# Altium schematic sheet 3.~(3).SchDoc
size 420 x 297 mm
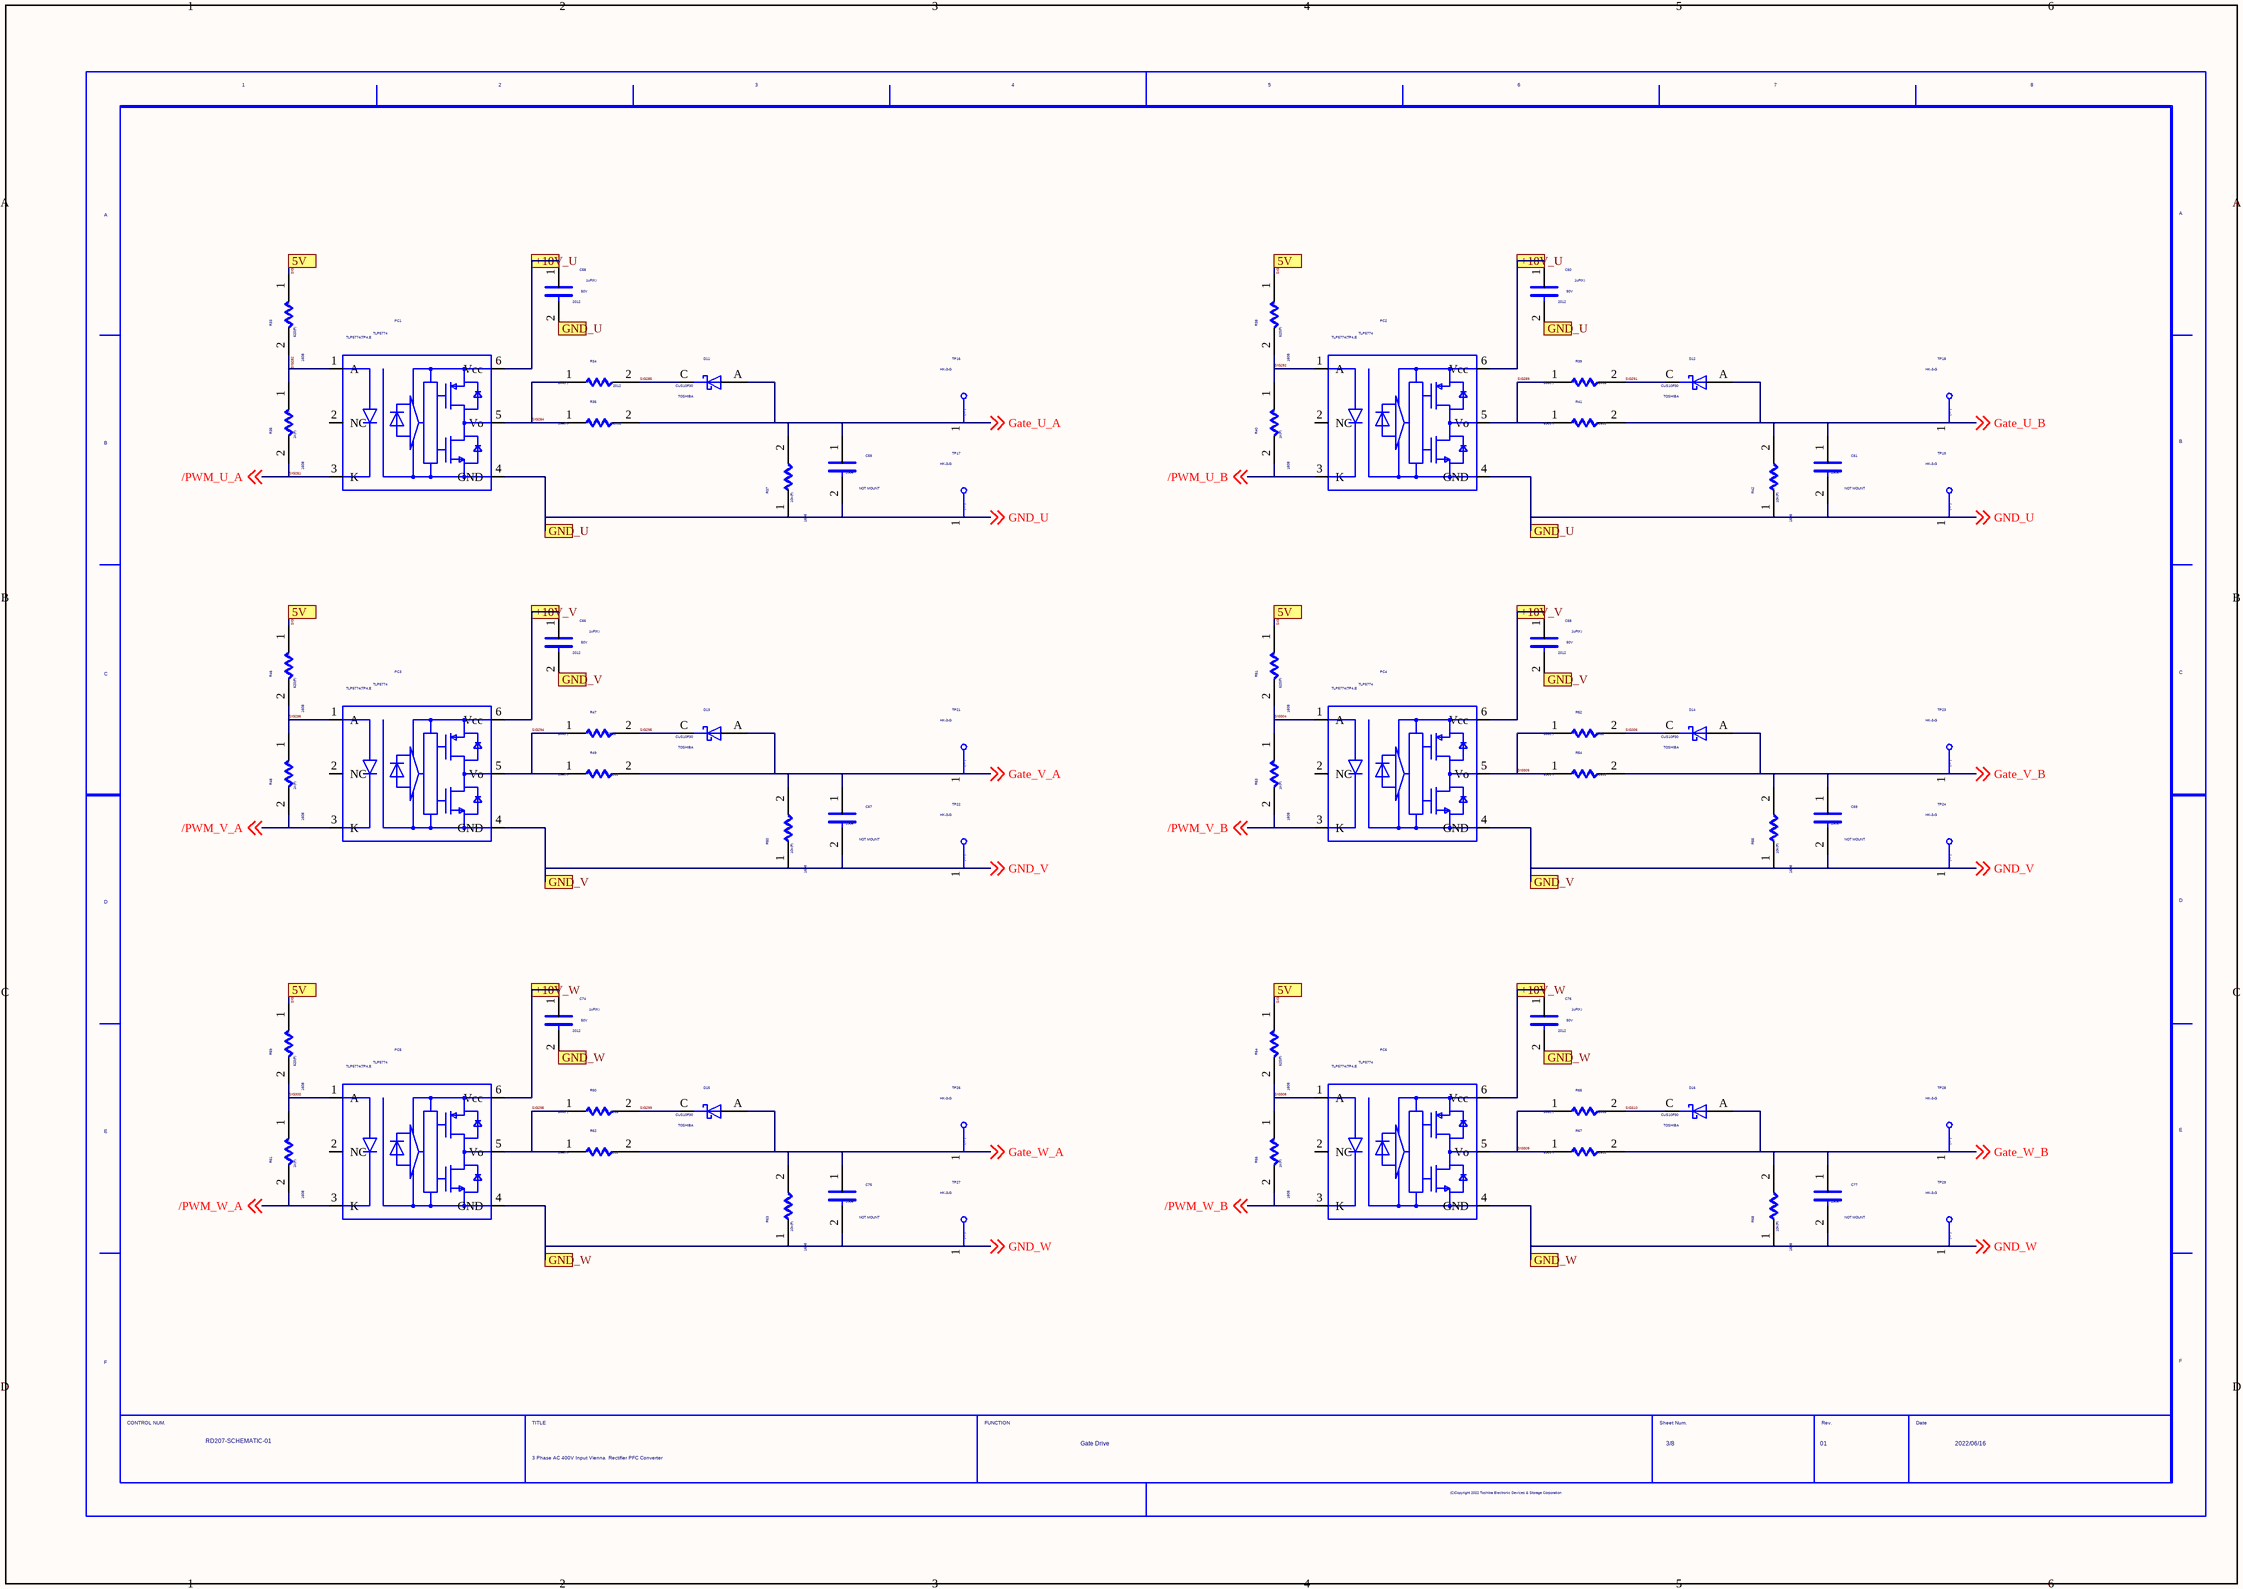
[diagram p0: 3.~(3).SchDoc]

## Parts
C58  SIZECODESMD: 2012  VAL2: 50V  VAL1: 1uF(K)  (hidden comment: C)
C59  SIZECODESMD: 1608  NOTMOUNT: NOT MOUNT  (hidden comment: C)
C60  SIZECODESMD: 2012  VAL2: 50V  VAL1: 1uF(K)  (hidden comment: C)
C61  SIZECODESMD: 1608  NOTMOUNT: NOT MOUNT  (hidden comment: C)
C66  SIZECODESMD: 2012  VAL2: 50V  VAL1: 1uF(K)  (hidden comment: C)
C67  SIZECODESMD: 1608  NOTMOUNT: NOT MOUNT  (hidden comment: C)
C68  SIZECODESMD: 2012  VAL2: 50V  VAL1: 1uF(K)  (hidden comment: C)
C69  SIZECODESMD: 1608  NOTMOUNT: NOT MOUNT  (hidden comment: C)
C74  SIZECODESMD: 2012  VAL2: 50V  VAL1: 1uF(K)  (hidden comment: C)
C75  SIZECODESMD: 1608  NOTMOUNT: NOT MOUNT  (hidden comment: C)
C76  SIZECODESMD: 2012  VAL2: 50V  VAL1: 1uF(K)  (hidden comment: C)
C77  SIZECODESMD: 1608  NOTMOUNT: NOT MOUNT  (hidden comment: C)
D11  USERCOMPTEXT3: TOSHIBA  VAL3: CUS10F30  (hidden comment: SBD)
D12  USERCOMPTEXT3: TOSHIBA  VAL3: CUS10F30  (hidden comment: SBD)
D13  USERCOMPTEXT3: TOSHIBA  VAL3: CUS10F30  (hidden comment: SBD)
D14  USERCOMPTEXT3: TOSHIBA  VAL3: CUS10F30  (hidden comment: SBD)
D15  USERCOMPTEXT3: TOSHIBA  VAL3: CUS10F30  (hidden comment: SBD)
D16  USERCOMPTEXT3: TOSHIBA  VAL3: CUS10F30  (hidden comment: SBD)
PC1  TLP5774  VAL3: TLP5774(TP4,E
PC2  TLP5774  VAL3: TLP5774(TP4,E
PC3  TLP5774  VAL3: TLP5774(TP4,E
PC4  TLP5774  VAL3: TLP5774(TP4,E
PC5  TLP5774  VAL3: TLP5774(TP4,E
PC6  TLP5774  VAL3: TLP5774(TP4,E
R33  SIZECODESMD: 1608  VAL1: 620(F)  (hidden comment: R)
R34  SIZECODESMD: 2012  VAL1: 100(F)  (hidden comment: R)
R35  SIZECODESMD: 1608  VAL1: 1k(F)  (hidden comment: R)
R36  SIZECODESMD: 2012  VAL1: 100(F)  (hidden comment: R)
R37  SIZECODESMD: 1608  VAL1: 10k(F)  (hidden comment: R)
R38  SIZECODESMD: 1608  VAL1: 620(F)  (hidden comment: R)
R39  SIZECODESMD: 2012  VAL1: 100(F)  (hidden comment: R)
R40  SIZECODESMD: 1608  VAL1: 1k(F)  (hidden comment: R)
R41  SIZECODESMD: 2012  VAL1: 100(F)  (hidden comment: R)
R42  SIZECODESMD: 1608  VAL1: 10k(F)  (hidden comment: R)
R46  SIZECODESMD: 1608  VAL1: 620(F)  (hidden comment: R)
R47  SIZECODESMD: 2012  VAL1: 100(F)  (hidden comment: R)
R48  SIZECODESMD: 1608  VAL1: 1k(F)  (hidden comment: R)
R49  SIZECODESMD: 2012  VAL1: 100(F)  (hidden comment: R)
R50  SIZECODESMD: 1608  VAL1: 10k(F)  (hidden comment: R)
R51  SIZECODESMD: 1608  VAL1: 620(F)  (hidden comment: R)
R52  SIZECODESMD: 2012  VAL1: 100(F)  (hidden comment: R)
R53  SIZECODESMD: 1608  VAL1: 1k(F)  (hidden comment: R)
R54  SIZECODESMD: 2012  VAL1: 100(F)  (hidden comment: R)
R55  SIZECODESMD: 1608  VAL1: 10k(F)  (hidden comment: R)
R59  SIZECODESMD: 1608  VAL1: 620(F)  (hidden comment: R)
R60  SIZECODESMD: 2012  VAL1: 100(F)  (hidden comment: R)
R61  SIZECODESMD: 1608  VAL1: 1k(F)  (hidden comment: R)
R62  SIZECODESMD: 2012  VAL1: 100(F)  (hidden comment: R)
R63  SIZECODESMD: 1608  VAL1: 10k(F)  (hidden comment: R)
R64  SIZECODESMD: 1608  VAL1: 620(F)  (hidden comment: R)
R65  SIZECODESMD: 2012  VAL1: 100(F)  (hidden comment: R)
R66  SIZECODESMD: 1608  VAL1: 1k(F)  (hidden comment: R)
R67  SIZECODESMD: 2012  VAL1: 100(F)  (hidden comment: R)
R68  SIZECODESMD: 1608  VAL1: 10k(F)  (hidden comment: R)
TP16  VAL3: HK-3-G  (hidden comment: TP)
TP17  VAL3: HK-3-G  (hidden comment: TP)
TP18  VAL3: HK-3-G  (hidden comment: TP)
TP19  VAL3: HK-3-G  (hidden comment: TP)
TP21  VAL3: HK-3-G  (hidden comment: TP)
TP22  VAL3: HK-3-G  (hidden comment: TP)
TP23  VAL3: HK-3-G  (hidden comment: TP)
TP24  VAL3: HK-3-G  (hidden comment: TP)
TP26  VAL3: HK-3-G  (hidden comment: TP)
TP27  VAL3: HK-3-G  (hidden comment: TP)
TP28  VAL3: HK-3-G  (hidden comment: TP)
TP29  VAL3: HK-3-G  (hidden comment: TP)
U?  DATE: 2022/06/16  TITLE: 3 Phase AC 400V Input Vienna / Rectifier PFC Converter  REVISION: 01  SHEETNUMBER: 3/8  FUNCTION: Gate Drive  DRAWINGNUMBER: RD207-SCHEMATIC-01  (hidden comment: WAKU_DEF100)

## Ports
5V, +10V_U, +10V_V, +10V_W, GND_U, GND_V, GND_W

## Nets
+10V_V: C66.1 C68.1 PC3.6(Vcc) PC4.6(Vcc) ; port +10V_V
+10V_W: C74.1 C76.1 PC5.6(Vcc) PC6.6(Vcc) ; port +10V_W
/PWM_U_B: PC2.3(K) R40.2 ; off-sheet /PWM_U_B
/PWM_V_A: PC3.3(K) R48.2 ; off-sheet /PWM_V_A
/PWM_V_B: PC4.3(K) R53.2 ; off-sheet /PWM_V_B
/PWM_W_A: PC5.3(K) R61.2 ; off-sheet /PWM_W_A
/PWM_W_B: PC6.3(K) R66.2 ; off-sheet /PWM_W_B
Gate_U_A: C59.1 D11.A R36.2 R37.2 TP16.1 ; off-sheet Gate_U_A
Gate_U_B: C61.1 D12.A R41.2 R42.2 TP18.1 ; off-sheet Gate_U_B
Gate_V_A: C67.1 D13.A R49.2 R50.2 TP21.1 ; off-sheet Gate_V_A
Gate_V_B: C69.1 D14.A R54.2 R55.2 TP23.1 ; off-sheet Gate_V_B
Gate_W_A: C75.1 D15.A R62.2 R63.2 TP26.1 ; off-sheet Gate_W_A
Gate_W_B: C77.1 D16.A R67.2 R68.2 TP28.1 ; off-sheet Gate_W_B
GND_U: C58.2 C59.2 C60.2 C61.2 PC1.4(GND) PC2.4(GND) R37.1 R42.1 TP17.1 TP19.1 ; off-sheet GND_U, port GND_U
GND_V: C66.2 C67.2 C68.2 C69.2 PC3.4(GND) PC4.4(GND) R50.1 R55.1 TP22.1 TP24.1 ; off-sheet GND_V, port GND_V
GND_W: C74.2 C75.2 C76.2 C77.2 PC5.4(GND) PC6.4(GND) R63.1 R68.1 TP27.1 TP29.1 ; off-sheet GND_W, port GND_W
SIG280: R33.1 R38.1 R46.1 R51.1 R59.1 R64.1 ; port 5V  [also labelled SIG293, SIG297, SIG301, SIG303, SIG307]
SIG281: PC1.3(K) R35.2 ; off-sheet /PWM_U_A  [also labelled /PWM_U_A]
SIG282: PC1.1(A) R33.2 R35.1
SIG284: PC1.5(Vo) R34.1 R36.1
SIG285: D11.C R34.2
SIG287: C58.1 C60.1 PC1.6(Vcc) PC2.6(Vcc) ; port +10V_U  [also labelled SIG288]
SIG289: PC2.5(Vo) R39.1 R41.1
SIG291: D12.C R39.2
SIG292: PC2.1(A) R38.2 R40.1
SIG294: PC3.5(Vo) R47.1 R49.1
SIG295: D13.C R47.2
SIG296: PC3.1(A) R46.2 R48.1
SIG298: PC5.5(Vo) R60.1 R62.1
SIG299: D15.C R60.2
SIG300: PC5.1(A) R59.2 R61.1
SIG304: PC4.1(A) R51.2 R53.1
SIG305: PC4.5(Vo) R52.1 R54.1
SIG306: D14.C R52.2
SIG308: PC6.1(A) R64.2 R66.1
SIG309: PC6.5(Vo) R65.1 R67.1
SIG310: D16.C R65.2

Not connected (* = marked no-connect by the designer): PC1 2(NC); PC2 2(NC); PC3 2(NC); PC4 2(NC); PC5 2(NC); PC6 2(NC)

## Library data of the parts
C58 C60 C66 C68 C74 C76 = C: OriginalSymbolOrigin: (2540,7620); COMP: C-UMK212B7105KGHT
C59 C61 C67 C69 C75 C77 = C: OriginalSymbolOrigin: (2540,7620); COMP: -C-NC_C1608
D11-D16 = SBD: SAVEAREA0: -4630,-153,17114,13055; TIME: 14:49:55; UPDATEUSER: fukuda-y; UPDATETIME: 08:16:22; SAVECOUNT: 9; OriginalSymbolOrigin: (5080,5080); COMP: -D-CUS10F30_AC
PC1-PC6 = TLP5774: Photocouplers; COMP: PC-TLP5774H_TP4_E; MAKER: TOSHIBA; NOTE: 5kV 8mm; TIME: 11:39:41; UPDATEUSER: t5459927; UPDATETIME: 14:14:00; SAVECOUNT: 2; SAVEAREA0: -5083,-25908,32249,1421; OriginalSymbolOrigin: (0,0)
R33 R38 R46 R51 R59 R64 = R: OriginalSymbolOrigin: (5080,5080); VAL2: 125mW; COMP: -R-RK73H1JTTD6200F
R34 R36 R39 R41 R47 R49 R52 R54 R60 R62 R65 R67 = R: OriginalSymbolOrigin: (5080,5080); VAL2: 250mW; COMP: -R-RK73H2ARTTD10R0F
R35 R40 R48 R53 R61 R66 = R: OriginalSymbolOrigin: (5080,5080); VAL2: 125mW; COMP: -R-RK73H1JTTD1001F
R37 R42 R50 R55 R63 R68 = R: OriginalSymbolOrigin: (5080,5080); VAL2: 100mW; COMP: -R-ERJ3EKF1002V
TP16-TP19 TP21-TP24 TP26-TP29 = TP: TIME: 16:12:21; UPDATEUSER: fukuda-y; UPDATETIME: 16:18:11; SAVECOUNT: 2; SAVEAREA0: -242,-92,12810,7836; OriginalSymbolOrigin: (0,7620); COMP: -TP-HK-3-G
U? = WAKU_DEF100: PLOTTIME: HH:MM; SAVEAREA0: 22200,72372,612276,319236; TIME: 14:30:25; UPDATEUSER: t5459927; UPDATETIME: 09:21:32; SAVECOUNT: 7; OriginalSymbolOrigin: (10160,284480)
